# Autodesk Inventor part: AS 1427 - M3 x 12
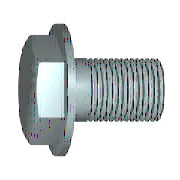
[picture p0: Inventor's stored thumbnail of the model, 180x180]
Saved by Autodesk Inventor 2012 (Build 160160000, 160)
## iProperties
IsCustomPart: 0
Created: 2011-02
Part Number: AS 1427 - M3 x 12
Material: Steel, Mild
Description: ISO metric machine screws
Document SubType Name: Modeling
Standard: AS 1427
Designer: Admin
Standards Organization: AS
Language: en-US
Size Designation: M3 x 12
Categories: <MemberInstance><Categories><Category DisplayName="Fasteners" InternalName="e4da775c-781d-43d5-af7c-5136215cf5a6" Mnemonic="FSTN"><Category DisplayName="Bolts"
Density: 1 g/cm^3
Author: Admin
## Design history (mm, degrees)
workplane "Work Plane1"
revolve "Body" stored, may be unused: angle "d12" = 90 deg
sketch "Sketch2"
  geometry: L1 (0, 2.887)-(2.5, 1.443); L2 (2.5, 1.443)-(2.5, -1.443); L3 (2.5, -1.443)-(0, -2.887); L4 (0, -2.887)-(-2.5, -1.443); L5 (-2.5, -1.443)-(-2.5, 1.443); L6 (-2.5, 1.443)-(0, 2.887); C1 r 3.375 at (0, 0) reference; C2 r 3.375 at (0, 0) reference; 1 further point
  constraints: 12 end point, 1 coincident, 1 vertical, 11 other
  dimensions: "d10" = 5 distance between parallel lines of L5 L2 (= SW)
extrude "Head" join sketch "Sketch2" distance "d3" = 2.36 (= KOH); taper "d4" = 0 deg
revolve "Chamfer1" stored, may be unused: angle "d21" = 90 deg
body "Solid1"
feature "Thread" dims "d13" = 11 (= GEL), "d14" = 0
chamfer "Chamfer2" distance "d6" = 0.30673 (= -0.5 x SPD + 0.5 x GD); stored, may be unused: second distance "d7" = 0.30673 (= -0.5 x SPD + 0.5 x GD), angle "d41" = 45 deg
sketch "Sketch1"
  geometry: L1 (0, 3.375)-(0, 1.193); L2 (1, 1.5)-(12, 1.5); L3 (12, 1.5)-(12, 0); L4 (12, 0)-(-0.53, 0); L5 (0, -0.675)-(0, 4.05) reference; L6 (-3.036, 0)-(14.506, 0) reference; L7 (-0.53, 0)-(-0.53, 3.375); L8 (-0.53, 3.375)-(0, 3.375); L9 (1, 1.5)-(0.693, 1.193); L10 (0.693, 1.193)-(0, 1.193)
  constraints: 16 end point, 2 perpendicular, 2 point on line, 1 collinear, 1 parallel
  dimensions: "d0" = 12 distance between parallel lines of L3 L1 (= NLG); "d1" = 11 distance from line of L2.start L3 (= GEL); "d2" = 3 diameter of L2 L4 (= GD); "d8" = 0.53 distance between parallel lines of L7 L1 (= PHH); "d9" = 6.75 diameter of L8 L4 (= LADI); "d15" = 2.38655 diameter of L10 L4 (= BDM); "d16" = 0.30673 horizontal distance of L2.start L9.end (= GAL)
sketch "Sketch3"
  geometry: L1 (-2.36, 2.25)-(-2.36, 2.887); L2 (-2.36, 2.887)-(-1.992, 2.887); L3 (-1.992, 2.887)-(-2.36, 2.25); L4 (-1.765, 2.887)-(-2.36, 2.887); L5 (-2.36, 2.887)-(-2.36, 0.577); L6 (-0.53, 2.887)-(-2.36, 2.887) reference; L7 (-2.36, 2.887)-(-2.36, 1.443) reference; L8 (-2.726, 0)-(-0.164, 0) reference
  constraints: 10 end point, 4 collinear, 1 perpendicular, 1 vertical
  dimensions: "d5" = 30 deg angle of L3 L1 (= ANG1); "d18" = 4.5 diameter of L1.start L8 (= SW0)
other parameters: "NLG" = 12 [user parameter; used in 1 equation term], "GD" = 3 (= NND) [user parameter; used in 3 equation terms], "BDM" = 2.38655 (= NND - 1.2269 x PTC) [user parameter; used in 1 equation term], "KOH" = 2.36 [user parameter; used in 1 equation term], "GEL" = 11 [user parameter; used in 2 equation terms], "LADI" = 6.75 [user parameter; used in 1 equation term], "SW" = 5 [user parameter; used in 2 equation terms], "PHH" = 0.53 [user parameter; used in 2 equation terms], "SW0" = 4.5 [user parameter; used in 1 equation term], "SPD" = 2.38655 (= NND - 1.2269 x PTC) [user parameter; used in 2 equation terms], "ANG1" = 30 deg [user parameter; used in 1 equation term], "GAL" = 0.30673 (= 0.61345 x PTC) [user parameter; used in 1 equation term], "GUL" = 0.30673 (= 0.61345 x PTC) [user parameter], "d17" = 0, "d42" = 0, "d43" = 0, "WFT" = 0.53 (= PHH) [user parameter], "PTC" = 0.5 [user parameter; used in 6 equation terms], "THREADDIA" = 3 [user parameter; used in 1 equation term], "E0" = 5.775 (= 1.155 x SW) [user parameter], "TOA" = 30 deg [user parameter], "NND" = 3 [user parameter; used in 4 equation terms], "GD1" = 2.38655 (= THREADDIA - 1.2269 x PTC) [user parameter], "SDH" = 3.6 [user parameter], "KOH1" = 1.83 [user parameter], "SD2" = 3 (= NND) [user parameter], "SD" = 0 [user parameter], "RR" = 0.1 [user parameter]
